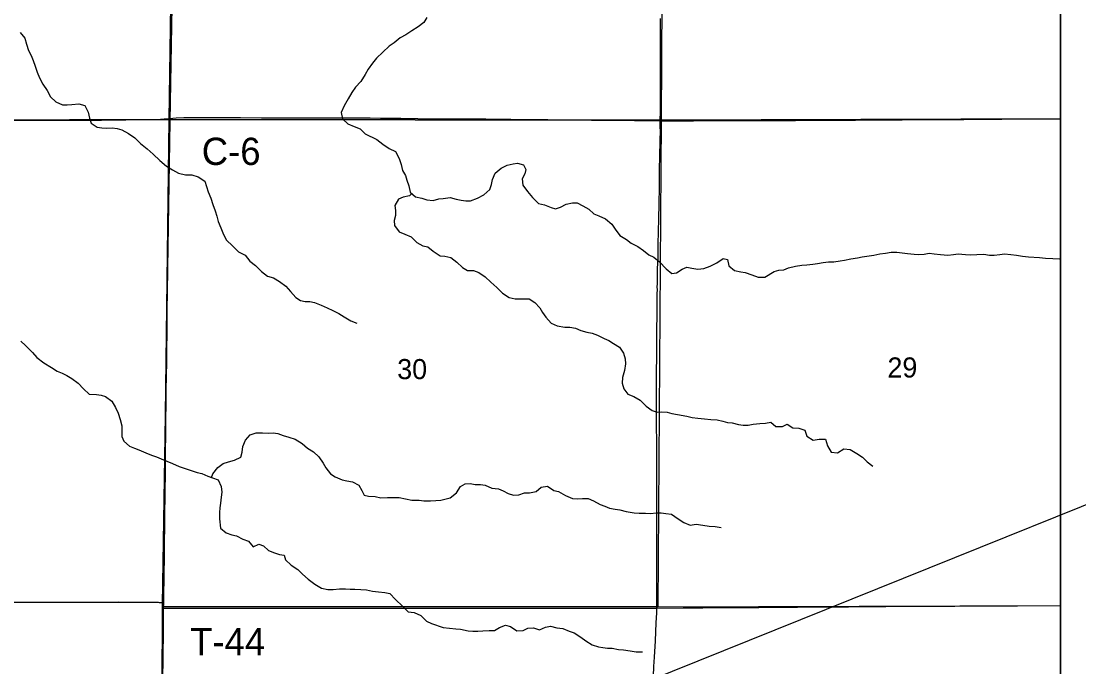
# Model space of a CAD drawing. Extents: x 0 to 34, y 0 to 22.
# Drawn here: x 8.318 to 9.419, y 14.835 to 15.508 of the extents above; entities that cross this region are included whole.
import ezdxf

# ---------------------------------------------------------------- set-up
doc = ezdxf.new("R2010")
doc.units = 0
for name, color, linetype in [('GM_X_County', 7, 'Continuous'), ('GM_X_County_Road', 7, 'Continuous'), ('GM_X_County_Road_Text', 7, 'Continuous'), ('GM_X_Minor_River', 7, 'Continuous'), ('GM_X_Section', 7, 'Continuous'), ('GM_X_Section_Text', 7, 'Continuous'), ('GM_X_Township', 7, 'Continuous'), ('GM_X_Township_Road', 7, 'Continuous'), ('GM_X_Township_Road_Text', 7, 'Continuous'), ('SH_Data', 7, 'Continuous'), ('SH_Text', 7, 'Continuous')]:
    doc.layers.add(name, color=color, linetype=linetype)

msp = doc.modelspace()

# ---------------------------------------------------------------- linework, layer by layer
at = {"layer": 'GM_X_County'}
msp.add_lwpolyline([(9.4, 14.3965), (9.4, 20.9), (2.6, 20.9), (2.6, 14.4092)], dxfattribs=at)
at = {"layer": 'GM_X_County_Road'}
for points in [[(8.9833, 15.4039), (8.9833, 15.4054), (8.9834, 15.4125), (8.9834, 15.4222), (8.9835, 15.4377), (8.9835, 15.4433), (8.9835, 15.4539), (8.9836, 15.461), (8.9837, 15.4694), (8.9837, 15.4831), (8.9836, 15.5039), (8.9836, 15.5104)], [(8.3094, 15.4044), (8.3321, 15.4045), (8.3485, 15.4046), (8.3625, 15.4047), (8.3771, 15.4046), (8.3899, 15.4046), (8.4014, 15.4046), (8.4268, 15.4048), (8.4477, 15.4051), (8.4586, 15.4054), (8.4667, 15.4059), (8.4726, 15.4064)], [(8.4726, 15.4064), (8.4758, 15.4067), (8.4792, 15.407), (8.4873, 15.4073), (8.4998, 15.4074), (8.52, 15.4073), (8.5464, 15.4072), (8.5681, 15.4071), (8.5893, 15.407), (8.6005, 15.4071), (8.6085, 15.4071), (8.62, 15.4071), (8.634, 15.4071), (8.6502, 15.4071), (8.6642, 15.407), (8.6812, 15.4069), (8.6921, 15.4068), (8.7133, 15.4065), (8.731, 15.4064), (8.754, 15.4061), (8.7798, 15.406), (8.8018, 15.4059), (8.8276, 15.4056), (8.8475, 15.4054), (8.8661, 15.4052), (8.8873, 15.405), (8.9118, 15.4047), (8.9292, 15.4045), (8.9566, 15.4042), (8.9833, 15.4039)], [(8.9798, 14.8962), (8.9799, 14.8987), (8.9799, 14.9062), (8.9799, 14.9186), (8.9799, 14.927), (8.9799, 14.9314), (8.9799, 14.9394), (8.9799, 14.9581), (8.9799, 14.9665), (8.9798, 14.9736), (8.9798, 14.9792), (8.9798, 14.9851), (8.9798, 14.9919), (8.9798, 14.9975), (8.9797, 15.0109), (8.9797, 15.027), (8.9796, 15.0389), (8.9797, 15.0485), (8.9797, 15.0631), (8.9796, 15.0749), (8.9795, 15.0805), (8.9795, 15.0926), (8.9795, 15.1001), (8.9794, 15.1084), (8.9794, 15.1156), (8.9794, 15.1215), (8.9795, 15.1302), (8.9795, 15.1351), (8.9795, 15.1469), (8.9796, 15.1535), (8.9798, 15.173), (8.9799, 15.1808), (8.9799, 15.191), (8.98, 15.1969), (8.98, 15.2022), (8.9801, 15.2119), (8.9801, 15.2162), (8.9802, 15.2202), (8.9802, 15.224), (8.9803, 15.2277), (8.9802, 15.2308), (8.9803, 15.2342), (8.9803, 15.2373), (8.9803, 15.2445), (8.9803, 15.2466), (8.9804, 15.2487), (8.9808, 15.2568), (8.981, 15.2602), (8.9811, 15.2636), (8.9811, 15.2704), (8.9812, 15.2732), (8.9812, 15.2766), (8.9813, 15.2794), (8.9813, 15.2809), (8.9814, 15.2831), (8.9814, 15.2837), (8.9815, 15.2874), (8.9818, 15.3027), (8.9821, 15.3163), (8.9824, 15.3359), (8.9824, 15.3399), (8.9826, 15.3474), (8.9826, 15.3505), (8.9827, 15.3567), (8.9828, 15.3636), (8.9829, 15.3682), (8.983, 15.3732), (8.9831, 15.3763), (8.9831, 15.3772), (8.9833, 15.3868), (8.9834, 15.3905), (8.9834, 15.3943), (8.9833, 15.3964), (8.9833, 15.4007), (8.9833, 15.4039)], [(8.9833, 15.4039), (8.9864, 15.4038), (9.0181, 15.4039), (9.056, 15.4042), (9.0722, 15.4042), (9.1008, 15.4042), (9.1241, 15.4043), (9.1471, 15.4045), (9.1608, 15.4046), (9.1735, 15.4046), (9.1865, 15.4047), (9.2167, 15.4049), (9.2353, 15.405), (9.2562, 15.4051), (9.29, 15.4053), (9.2994, 15.4054), (9.3109, 15.4055), (9.3391, 15.4055), (9.3771, 15.4058), (9.3914, 15.4058), (9.4, 15.4059)], [(8.9762, 14.8255), (8.9767, 14.8354), (8.9772, 14.8453), (8.9782, 14.8621), (8.9792, 14.881), (8.9797, 14.8913), (8.9798, 14.8962)]]:
    msp.add_lwpolyline(points, dxfattribs=at)
at = {"layer": 'GM_X_Minor_River'}
for points in [[(8.7404, 15.5115), (8.7373, 15.5064), (8.7311, 15.5018), (8.7246, 15.4977), (8.7183, 15.4934), (8.7124, 15.4902), (8.7061, 15.4852), (8.701, 15.4815), (8.6945, 15.4754), (8.688, 15.469), (8.6836, 15.4641), (8.6792, 15.4578), (8.676, 15.4522), (8.6716, 15.4448), (8.6659, 15.4391), (8.6623, 15.4333), (8.6584, 15.4268), (8.6542, 15.4196), (8.6512, 15.4124), (8.6525, 15.406), (8.6581, 15.4006), (8.6646, 15.3979), (8.6708, 15.3954), (8.6761, 15.3905), (8.6882, 15.3844), (8.6943, 15.3796), (8.7009, 15.375), (8.7077, 15.3719), (8.7113, 15.3647), (8.7136, 15.3584), (8.7149, 15.352), (8.7179, 15.347), (8.7196, 15.3419), (8.7214, 15.336), (8.7229, 15.3297), (8.7284, 15.3248), (8.7352, 15.3234), (8.7402, 15.3215), (8.7468, 15.3209), (8.7527, 15.3226), (8.7574, 15.3231), (8.7645, 15.3239), (8.7709, 15.3223), (8.776, 15.3212), (8.7808, 15.3204), (8.7859, 15.3207), (8.7929, 15.3232), (8.7996, 15.3268), (8.8057, 15.3324), (8.8076, 15.3375)], [(8.3167, 15.4958), (8.3216, 15.4901), (8.3233, 15.4839), (8.3254, 15.477), (8.3284, 15.4721), (8.3304, 15.4669), (8.3325, 15.4609), (8.3344, 15.4546), (8.3368, 15.4487), (8.3404, 15.4422), (8.3449, 15.4354), (8.3485, 15.4289), (8.354, 15.4236), (8.3608, 15.4207), (8.3657, 15.4205), (8.3707, 15.421), (8.3779, 15.4216), (8.3843, 15.4197), (8.3877, 15.4128), (8.389, 15.4067), (8.3907, 15.4014), (8.3969, 15.3972), (8.4019, 15.3966), (8.4068, 15.3964), (8.4125, 15.3966), (8.4178, 15.396), (8.4226, 15.3944), (8.4296, 15.3906), (8.4362, 15.386), (8.442, 15.3803), (8.449, 15.3748), (8.4553, 15.3692), (8.4623, 15.3626), (8.4693, 15.3568), (8.4755, 15.3528), (8.4816, 15.3492), (8.4888, 15.3478)], [(8.8076, 15.3375), (8.8088, 15.3427), (8.8115, 15.3493), (8.8176, 15.3546), (8.8238, 15.3576), (8.8301, 15.3591), (8.8348, 15.3598), (8.8409, 15.3581), (8.8434, 15.3533), (8.8424, 15.3486), (8.8397, 15.3433), (8.8403, 15.337), (8.845, 15.3304), (8.8503, 15.3241), (8.8567, 15.3176), (8.8629, 15.3164), (8.8696, 15.3137), (8.8743, 15.3122), (8.8793, 15.3141), (8.8853, 15.3171), (8.8918, 15.3186), (8.8967, 15.3184), (8.9028, 15.3153), (8.909, 15.3117), (8.9143, 15.3071), (8.9193, 15.3048), (8.9263, 15.3019), (8.9329, 15.2962), (8.9365, 15.2911), (8.9414, 15.2846), (8.9482, 15.2802), (8.9531, 15.2764), (8.9599, 15.2731), (8.966, 15.2687), (8.9715, 15.2643), (8.9766, 15.2617), (8.9827, 15.2569), (8.9895, 15.2498), (8.9953, 15.2449), (9.0004, 15.2456), (9.0062, 15.2494), (9.0111, 15.2514), (9.0162, 15.2503), (9.0225, 15.2495), (9.0287, 15.25), (9.0354, 15.2525), (9.0422, 15.2561), (9.0487, 15.2604), (9.0535, 15.2594), (9.0548, 15.2528), (9.0606, 15.248), (9.0671, 15.2467), (9.0718, 15.2459), (9.0786, 15.2434), (9.0853, 15.2411), (9.0923, 15.2412), (9.1018, 15.2469), (9.1067, 15.2484), (9.1119, 15.2487), (9.117, 15.2506), (9.1242, 15.2525), (9.1307, 15.2536), (9.136, 15.2539), (9.1421, 15.2545), (9.147, 15.2552), (9.1531, 15.2563), (9.1586, 15.2569), (9.1641, 15.2569), (9.1706, 15.258), (9.1753, 15.2587), (9.1816, 15.26), (9.1886, 15.2611), (9.1935, 15.2622), (9.1985, 15.263), (9.2057, 15.2639), (9.2118, 15.2652), (9.2177, 15.2661), (9.2239, 15.2669), (9.2298, 15.267), (9.2351, 15.2664), (9.2408, 15.2658), (9.2476, 15.2649), (9.2526, 15.2648), (9.2581, 15.265), (9.2632, 15.2661), (9.2685, 15.2655), (9.275, 15.2647), (9.2826, 15.2641), (9.2886, 15.2647), (9.2934, 15.2654), (9.301, 15.2646), (9.3063, 15.2644), (9.3129, 15.2648), (9.3201, 15.2649), (9.3262, 15.2641), (9.3309, 15.2641), (9.337, 15.2647), (9.3418, 15.2652), (9.3482, 15.2646), (9.3543, 15.2638), (9.3604, 15.2629)], [(8.4888, 15.3478), (8.4956, 15.3476), (8.5023, 15.3457), (8.5091, 15.3409), (8.5108, 15.3354), (8.5126, 15.3299), (8.5153, 15.3234), (8.5175, 15.3168), (8.5198, 15.3103), (8.5216, 15.3046), (8.5231, 15.2991), (8.5256, 15.2923), (8.5286, 15.2856), (8.5318, 15.2797), (8.538, 15.2736), (8.5441, 15.2675), (8.5511, 15.2639), (8.5558, 15.2578), (8.5618, 15.2532), (8.5681, 15.2469), (8.5743, 15.242), (8.5806, 15.2402), (8.5868, 15.2366), (8.5933, 15.2316), (8.5982, 15.2261), (8.6037, 15.22), (8.6088, 15.2166), (8.6137, 15.2158), (8.6184, 15.2156), (8.6234, 15.2146), (8.6302, 15.2119), (8.6364, 15.2091), (8.6425, 15.2064), (8.6486, 15.2031), (8.6542, 15.1997), (8.6612, 15.1957), (8.6673, 15.1932)], [(8.7245, 15.3283), (8.7222, 15.3258), (8.7157, 15.3245), (8.7108, 15.3224), (8.7069, 15.3158), (8.7075, 15.3105), (8.7076, 15.3053), (8.7061, 15.3), (8.7066, 15.2949), (8.7114, 15.2881), (8.7174, 15.2857), (8.7239, 15.2829), (8.7297, 15.2773), (8.7362, 15.2737), (8.7413, 15.2725), (8.747, 15.268), (8.7542, 15.2634), (8.7589, 15.263), (8.7653, 15.2614), (8.7716, 15.2567), (8.7773, 15.2511), (8.7826, 15.2481), (8.789, 15.248), (8.7943, 15.2459), (8.8009, 15.2414), (8.8068, 15.2358), (8.813, 15.2301), (8.8191, 15.2244), (8.8261, 15.2198), (8.8322, 15.2184), (8.8384, 15.2186), (8.8468, 15.2184), (8.8527, 15.2148), (8.8578, 15.209), (8.8608, 15.2043), (8.8642, 15.1993), (8.8698, 15.1932), (8.8761, 15.1905), (8.8839, 15.189), (8.8892, 15.1888), (8.8949, 15.1878), (8.9007, 15.1855), (8.907, 15.1838), (8.9123, 15.1826), (8.9178, 15.1807), (8.925, 15.1772), (8.9299, 15.1749), (8.9348, 15.1721), (8.9409, 15.1681), (8.9452, 15.162), (8.9467, 15.1561), (8.9473, 15.1506), (8.9461, 15.1437), (8.944, 15.1365), (8.9438, 15.1307), (8.9453, 15.1248), (8.9496, 15.1193), (8.9557, 15.1168), (8.9623, 15.1129), (8.9685, 15.1065), (8.975, 15.1021), (8.9801, 15.1005), (8.985, 15.1007), (8.9905, 15.1005), (8.9955, 15.0991), (9.0012, 15.098), (9.011, 15.0964), (9.0167, 15.095), (9.0224, 15.0943), (9.0294, 15.0935), (9.0359, 15.0929), (9.0425, 15.0925), (9.0486, 15.0909), (9.0533, 15.0898), (9.0581, 15.0894), (9.0649, 15.0876), (9.0698, 15.087), (9.0747, 15.087), (9.0799, 15.0878), (9.0869, 15.0885), (9.0928, 15.089), (9.0985, 15.09), (9.1038, 15.0856), (9.1106, 15.0855), (9.1154, 15.0878), (9.1212, 15.0842), (9.1277, 15.0838), (9.1337, 15.0815), (9.136, 15.0754), (9.1426, 15.0714), (9.1489, 15.0723), (9.1553, 15.0722), (9.1576, 15.0654), (9.1614, 15.0586), (9.1678, 15.0582), (9.1743, 15.0623), (9.1809, 15.0615), (9.1879, 15.0575), (9.194, 15.0535), (9.1987, 15.0485), (9.2046, 15.0443)], [(9.3604, 15.2629), (9.3668, 15.2623), (9.3782, 15.2614), (9.3846, 15.2609), (9.3922, 15.2606), (9.3991, 15.2602), (9.4, 15.2602)], [(8.3174, 15.1744), (8.3224, 15.17), (8.3295, 15.1627), (8.3341, 15.1574), (8.3414, 15.1517), (8.3494, 15.1469), (8.3555, 15.1431), (8.3604, 15.141), (8.3653, 15.1385), (8.3706, 15.1354), (8.3772, 15.1305), (8.3829, 15.1248), (8.3888, 15.1192), (8.3962, 15.1188), (8.4011, 15.1182), (8.4058, 15.1167)], [(8.4058, 15.1167), (8.4121, 15.1117), (8.416, 15.1054), (8.4187, 15.0995), (8.4209, 15.0929), (8.4228, 15.0862), (8.4227, 15.075), (8.4246, 15.0703), (8.4307, 15.065), (8.4358, 15.0628), (8.4405, 15.0611), (8.4475, 15.0579), (8.4536, 15.0557), (8.4587, 15.054), (8.4638, 15.0517), (8.4697, 15.0492), (8.4754, 15.0471), (8.4822, 15.0439), (8.4885, 15.0416), (8.501, 15.0377), (8.5059, 15.0364), (8.5123, 15.0337), (8.5171, 15.0321), (8.5231, 15.03), (8.5261, 15.023), (8.5267, 15.0171), (8.5261, 15.012), (8.5253, 15.0057), (8.5247, 15.0006), (8.5243, 14.9959), (8.5243, 14.9894), (8.5254, 14.9797), (8.5314, 14.9746), (8.5373, 14.9726), (8.5421, 14.9715), (8.5485, 14.9682), (8.5546, 14.9659), (8.5593, 14.96), (8.5654, 14.9628), (8.5701, 14.9611), (8.5754, 14.9564), (8.5817, 14.9539), (8.5868, 14.9523), (8.5917, 14.9513), (8.5932, 14.9466), (8.5989, 14.9411), (8.6061, 14.9365), (8.6108, 14.9315), (8.6168, 14.9266), (8.6238, 14.9212), (8.6305, 14.917), (8.6373, 14.9158), (8.6426, 14.9158), (8.6493, 14.9164), (8.6555, 14.9162), (8.6605, 14.9161), (8.6652, 14.9159), (8.6715, 14.9157), (8.6775, 14.9153), (8.6836, 14.9139), (8.6899, 14.9133), (8.6965, 14.9127), (8.7016, 14.9114), (8.7075, 14.9053), (8.7148, 14.8982), (8.7209, 14.8923), (8.7272, 14.8917), (8.734, 14.8887), (8.7398, 14.8828), (8.7451, 14.8803), (8.7571, 14.8762), (8.7637, 14.8754), (8.7704, 14.8748), (8.7753, 14.8744), (8.7833, 14.8725), (8.788, 14.8723), (8.7933, 14.8721), (8.7984, 14.8726), (8.8051, 14.873), (8.8106, 14.873), (8.8161, 14.8762), (8.8222, 14.8786), (8.8273, 14.8773), (8.8339, 14.8725), (8.8404, 14.8728), (8.8453, 14.8755), (8.8514, 14.8756), (8.8575, 14.8735), (8.8638, 14.8763), (8.8691, 14.8775), (8.8757, 14.8757), (8.882, 14.8749), (8.8886, 14.8724), (8.8937, 14.8705), (8.9007, 14.8661), (8.9058, 14.8621), (8.9123, 14.8579), (8.9189, 14.856), (8.9236, 14.8552), (8.9284, 14.8546), (8.9333, 14.8544)], [(8.5159, 15.0325), (8.5175, 15.0361), (8.5226, 15.0429), (8.5283, 15.0469), (8.5337, 15.0488), (8.5401, 15.0504), (8.5466, 15.0535), (8.5479, 15.0589), (8.5485, 15.0648), (8.5516, 15.0713), (8.5562, 15.0767), (8.5624, 15.079), (8.5693, 15.0788), (8.5753, 15.0786), (8.5801, 15.0787), (8.5852, 15.0783), (8.5907, 15.0762), (8.5966, 15.0745), (8.6032, 15.0722), (8.6104, 15.0676), (8.6161, 15.0628), (8.6221, 15.0592), (8.6278, 15.0539), (8.6322, 15.0474), (8.635, 15.0424), (8.6399, 15.0362), (8.6448, 15.0329), (8.652, 15.0298), (8.6568, 15.0289), (8.6628, 15.0277), (8.6693, 15.0245), (8.6725, 15.0187), (8.6749, 15.0138), (8.6796, 15.013), (8.6865, 15.0126), (8.6925, 15.0113), (8.6992, 15.0114), (8.7064, 15.0116), (8.7113, 15.0116), (8.7182, 15.0102), (8.7248, 15.0088), (8.7322, 15.0086), (8.7373, 15.0082), (8.744, 15.0082), (8.7495, 15.0083), (8.755, 15.0089), (8.7645, 15.0111), (8.771, 15.0162), (8.7752, 15.0228), (8.7803, 15.0257), (8.7854, 15.026), (8.7907, 15.0252), (8.7962, 15.0252), (8.801, 15.0243), (8.808, 15.0212), (8.8148, 15.0206), (8.8197, 15.0183), (8.825, 15.0156), (8.8304, 15.0139), (8.8359, 15.0142), (8.8421, 15.0165), (8.8471, 15.0163), (8.8541, 15.0178), (8.8594, 15.0221), (8.8659, 15.0232), (8.8725, 15.0188), (8.8773, 15.0177), (8.8846, 15.0136), (8.892, 15.0104), (8.8968, 15.0102), (8.9023, 15.0103), (8.9083, 15.0103), (8.9137, 15.0082), (8.9209, 15.0042), (8.9256, 15.0025), (8.9305, 15.0005), (8.9364, 14.9994), (8.9413, 14.9986), (8.9478, 14.9969), (8.9563, 14.9955), (8.9614, 14.9953), (8.9679, 14.9951), (8.9732, 14.995), (8.9789, 14.9954), (8.9842, 14.9954), (8.9891, 14.995), (8.995, 14.994), (9.0018, 14.9894), (9.0079, 14.9854), (9.0145, 14.9827), (9.0208, 14.9836), (9.0278, 14.9827), (9.0343, 14.9815), (9.0405, 14.9813), (9.0468, 14.9803)], [(8.9333, 14.8544), (8.9398, 14.853), (8.9451, 14.8528), (8.9519, 14.8518), (8.9582, 14.8509), (8.9648, 14.8507)]]:
    msp.add_lwpolyline(points, dxfattribs=at)
at = {"layer": 'GM_X_Section'}
for p, q in [((9.4, 15.4061), (9.4, 15.9093)), ((9.4, 14.8991), (9.4, 15.4061))]:
    msp.add_line(p, q, dxfattribs=at)
for points in [[(7.9595, 15.9031), (8.4794, 15.9082), (8.4718, 15.4054), (7.9519, 15.4037)], [(8.4794, 15.9082), (8.9872, 15.9088), (8.9843, 15.4045), (8.4718, 15.4054)], [(7.9519, 15.4037), (8.4718, 15.4054), (8.4656, 14.9022), (7.9571, 14.9016)], [(8.4718, 15.4054), (8.9843, 15.4045), (8.9808, 14.8977), (8.4656, 14.8977), (8.4656, 14.9022)]]:
    msp.add_lwpolyline(points, close=True, dxfattribs=at)
for points in [[(9.4, 15.9093), (8.9872, 15.9088), (8.9843, 15.4045), (9.4, 15.4061)], [(9.4, 15.4061), (8.9843, 15.4045), (8.9808, 14.8977), (9.4, 14.8991)]]:
    msp.add_lwpolyline(points, dxfattribs=at)
at = {"layer": 'GM_X_Township'}
msp.add_line((9.4, 14.3965), (9.4, 17.4092), dxfattribs=at)
for points in [[(8.4927, 17.4064), (8.489, 16.9129), (8.4875, 16.7165), (8.4852, 16.414), (8.4805, 15.9065), (8.4802, 15.8707), (8.4804, 15.8413), (8.4727, 15.4034), (8.4648, 14.9001), (8.4648, 14.8948), (8.4627, 14.3996), (8.4614, 14.3995), (7.9281, 14.4004), (7.4546, 14.4002), (7.1373, 14.3989)], [(9.4, 17.4092), (8.9926, 17.4083), (8.965, 17.4081), (8.4927, 17.4064), (8.489, 16.9129), (8.4875, 16.7165), (8.4852, 16.414), (8.4805, 15.9065), (8.4802, 15.8707), (8.4804, 15.8413), (8.4727, 15.4034), (8.4648, 14.9001), (8.4648, 14.8948), (8.4627, 14.3996), (8.961, 14.3984), (8.9649, 14.3985), (9.4, 14.3965)]]:
    msp.add_lwpolyline(points, dxfattribs=at)
at = {"layer": 'GM_X_Township_Road'}
for points in [[(8.4726, 15.4064), (8.4727, 15.4093), (8.4727, 15.4127), (8.4728, 15.4198), (8.4728, 15.4292), (8.4729, 15.4385), (8.473, 15.4416), (8.4732, 15.4537), (8.4733, 15.4621), (8.4735, 15.4767), (8.4736, 15.4804), (8.4737, 15.4913), (8.4738, 15.496), (8.474, 15.5106), (8.4743, 15.5364), (8.4745, 15.5435), (8.4747, 15.5572), (8.4747, 15.5693), (8.4751, 15.5951), (8.4753, 15.6168), (8.4753, 15.6237), (8.4754, 15.6467), (8.4754, 15.6468)], [(8.4696, 15.1591), (8.47, 15.1899), (8.47, 15.2085), (8.4702, 15.2238), (8.4704, 15.2508), (8.4705, 15.2648), (8.471, 15.299), (8.4712, 15.3167), (8.4717, 15.3465), (8.4719, 15.3583), (8.4721, 15.3698), (8.4724, 15.3891), (8.4725, 15.4015), (8.4726, 15.4059), (8.4726, 15.4064)], [(8.4663, 14.9014), (8.4665, 14.9111), (8.4667, 14.9263), (8.467, 14.9543), (8.4675, 14.9922), (8.4678, 15.0158), (8.4681, 15.0385), (8.4683, 15.06), (8.4685, 15.0761), (8.4686, 15.0911), (8.4689, 15.1106), (8.469, 15.1274), (8.4692, 15.1336), (8.4696, 15.1569), (8.4696, 15.1591)], [(8.3097, 14.9026), (8.3515, 14.9025), (8.3959, 14.9026), (8.4196, 14.9027), (8.445, 14.9026), (8.4569, 14.9026), (8.4579, 14.9026), (8.4588, 14.9026), (8.4597, 14.9025), (8.4606, 14.9024), (8.4615, 14.9023), (8.4648, 14.9017), (8.4663, 14.9014)], [(8.4662, 14.8964), (8.4663, 14.9014)], [(8.4651, 14.7479), (8.4652, 14.7557), (8.4653, 14.7756), (8.4654, 14.7883), (8.4654, 14.8045), (8.4655, 14.8197), (8.4658, 14.8462), (8.4659, 14.8716), (8.4662, 14.894), (8.4662, 14.8964)], [(8.4662, 14.8964), (8.4699, 14.8963), (8.4736, 14.8962), (8.4826, 14.8962), (8.5007, 14.8962), (8.5498, 14.8963), (8.5622, 14.8962), (8.5718, 14.8962), (8.5967, 14.8962), (8.6178, 14.8962), (8.6452, 14.8962), (8.657, 14.8964), (8.6663, 14.8964), (8.685, 14.8963), (8.6999, 14.8963), (8.7136, 14.8963), (8.7288, 14.8963), (8.7524, 14.8962), (8.7711, 14.8961), (8.7903, 14.8962), (8.8167, 14.8961), (8.8469, 14.8961), (8.8677, 14.8961), (8.8979, 14.8963), (8.9184, 14.8962), (8.9445, 14.8962), (8.969, 14.8961), (8.979, 14.8962), (8.9798, 14.8962)], [(8.9798, 14.8962), (9.0073, 14.8965), (9.0275, 14.8967), (9.0586, 14.8968), (9.0859, 14.897), (9.1263, 14.8972), (9.1621, 14.8975), (9.1795, 14.8977), (9.1978, 14.8978), (9.2183, 14.8979), (9.2522, 14.8982), (9.2901, 14.8984), (9.306, 14.8985), (9.3246, 14.8986), (9.3554, 14.8987), (9.4, 14.8989)]]:
    msp.add_lwpolyline(points, dxfattribs=at)
at = {"layer": 'SH_Data'}
msp.add_line((9.4, 20.9), (9.4, 14.1), dxfattribs=at)
at = {"layer": 'SH_Text'}
msp.add_lwpolyline([(9.8492, 15.1741), (7.9281, 14.4004), (9.8492, 14.9027)], close=True, dxfattribs=at)

# ---------------------------------------------------------------- texts
at = {"layer": 'GM_X_County_Road_Text'}
msp.add_text('C-6', height=0.02841, rotation=0, dxfattribs=at).set_placement((8.5059, 15.3579))
at = {"layer": 'GM_X_Section_Text'}
for s, p in [('30', (8.7094, 15.1348)), ('29', (9.2199, 15.1365))]:
    msp.add_text(s, height=0.02093, rotation=0, dxfattribs=at).set_placement(p)
at = {"layer": 'GM_X_Township_Road_Text'}
msp.add_text('T-44', height=0.02841, rotation=0, dxfattribs=at).set_placement((8.4938, 14.8472))

doc.saveas('drawing.dxf')
